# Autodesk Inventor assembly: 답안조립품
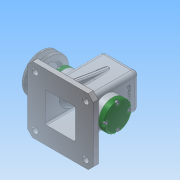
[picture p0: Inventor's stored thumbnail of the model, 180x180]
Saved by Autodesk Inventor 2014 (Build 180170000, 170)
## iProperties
Created: 2016-02
Part Number: 답안조립품
Document SubType Name: Assembly
Designer: net
Author: net
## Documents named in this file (16)
- C:\Users\net\Desktop\460211V1019\답안조립품.iam
- C:\Users\net\Desktop\460211V1019\본체.ipt
- C:\Users\net\Desktop\460211V1019\뒤커버.ipt
- C:\Users\net\Desktop\460211V1019\베어링 12 x 32 x 10.ipt
- C:\Users\net\Desktop\460211V1019\편심축.ipt
- C:\Users\net\Desktop\460211V1019\앞커버.ipt
- C:\Users\net\Desktop\460211V1019\오일실 12 25 7.ipt
- C:\Users\net\Desktop\460211V1019\키 4 x 4 x 10.ipt
- C:\Users\net\Desktop\460211V1019\V벨트풀리.ipt
- C:\Users\net\Desktop\460211V1019\멈춤나사 M3x8.ipt
- C:\Users\net\Desktop\460211V1019\링크.ipt
- C:\Users\net\Desktop\460211V1019\부시.ipt
- C:\Users\net\Desktop\460211V1019\슬라이드.ipt
- C:\Users\net\Desktop\460211V1019\핀 5 x 18.ipt
- C:\Users\net\Desktop\460211V1019\고정핀 1.2 x 10.ipt
- C:\Users\net\Desktop\460211V1019\볼트 M4 x 12.ipt
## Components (11 placed, 4 different names)
1. V벨트풀리:1 — 각도:2
2. 핀 5 x 18:1
3. 고정핀 1.2 x 10:1 — 각도:6
4. ISO 4762 M4 x 12:1
5. ISO 4762 M4 x 12:2
6. ISO 4762 M4 x 12:3
7. ISO 4762 M4 x 12:4
8. ISO 4762 M4 x 12:5
9. ISO 4762 M4 x 12:6
10. ISO 4762 M4 x 12:7
11. ISO 4762 M4 x 12:8
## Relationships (2: Angle 2)
- 각도:2 [Angle]: V벨트풀리:1
- 각도:6 [Angle]: 고정핀 1.2 x 10:1
